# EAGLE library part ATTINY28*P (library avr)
MICROCONTROLLER 1.8 V 2 Kbytes FLASH
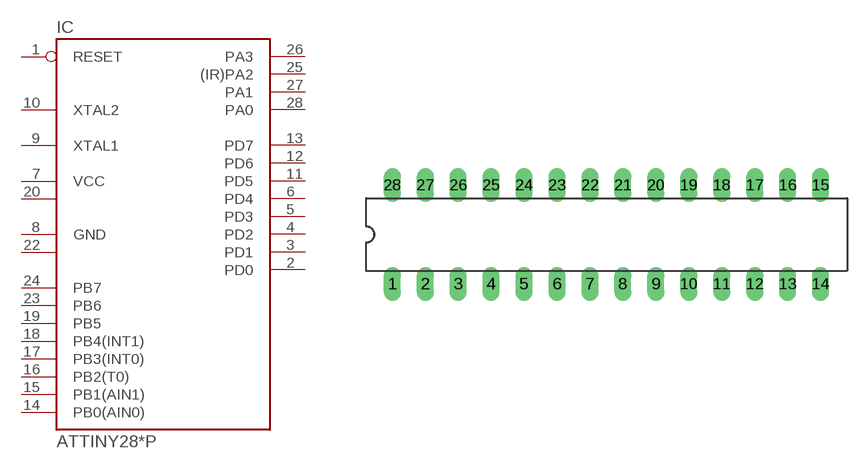
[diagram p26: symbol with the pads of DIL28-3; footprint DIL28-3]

Designator prefix IC

## ATTINY28L-4P, ATTINY28V-1P  [DIL28-3]
1  RESET  in
2  PD0
3  PD1
4  PD2
5  PD3
6  PD4
7  VCC  pwr
8  GND  pwr
9  XTAL1
10  XTAL2
11  PD5
12  PD6
13  PD7
14  PB0(AIN0)  in
15  PB1(AIN1)  in
16  PB2(T0)  in
17  PB3(INT0)  in
18  PB4(INT1)  in
19  PB5  in
20  VCC1  pwr
21  NC1  nc
22  GND1  pwr
23  PB6  in
24  PB7  in
25  (IR)PA2  out
26  PA3
27  PA1
28  PA0

## Footprint DIL28-3 (pad centres in mm)
Dual In Line 0.3 inch
drill 0.813 long: 1 -16.51,-3.81; 2 -13.97,-3.81; 3 -11.43,-3.81; 4 -8.89,-3.81; 5 -6.35,-3.81; 6 -3.81,-3.81; 7 -1.27,-3.81; 8 1.27,-3.81; 9 3.81,-3.81; 10 6.35,-3.81; 11 8.89,-3.81; 12 11.43,-3.81; 13 13.97,-3.81; 14 16.51,-3.81; 15 16.51,3.81; 16 13.97,3.81; 17 11.43,3.81; 18 8.89,3.81; 19 6.35,3.81; 20 3.81,3.81; 21 1.27,3.81; 22 -1.27,3.81; 23 -3.81,3.81; 24 -6.35,3.81; 25 -8.89,3.81; 26 -11.43,3.81; 27 -13.97,3.81; 28 -16.51,3.81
